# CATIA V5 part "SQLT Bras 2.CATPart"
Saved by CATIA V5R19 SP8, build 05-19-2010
Part number: SQLT Bras 2
Publications: "Droite.1", "Droite.2", "Droite.3", "Plan.1", "Plan.2"
Bounding box of the stored display mesh (mm): x -1000 to 1000, y 0 to 1200, z -1800 to -750
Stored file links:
  C:\Users\ThinkMotion\Desktop\EU_thinkMotion\iao\IAO_MMS_Groupe3\fovide\fovide\SQLT Bras 2.CATPart
  C:\Users\ThinkMotion\Desktop\EU_thinkMotion\iao\IAO_MMS_Groupe3\fovide\fovide\fovide.CATProduct
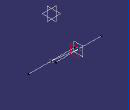
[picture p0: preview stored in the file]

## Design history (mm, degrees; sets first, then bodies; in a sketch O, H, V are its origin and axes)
External parameters (linked from other documents)
  `External.Diamètre bielle` = 150 mm
Set1
  Point1 "Point.B": linked copy from another document
  Point2 "Point.C": linked copy from another document
Set2 "set bras 2"
  Line1: type PtPt, FirstPoint Point1, SecondPoint Point2
  Line2: type Normal, RefPoint Point1, RefSkin yz-plane, Start -1000, End 1000
  Line3: type Normal, RefPoint Point2, RefSkin yz-plane, Start -1000, End 1000
  Plane1: type OffsetPt, RefPlane yz-plane, RefPoint Point1
  Plane2: type Offset, RefPlane Plane1, Offset 150 {= `External.Diamètre bielle`}
Body1 (main body)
